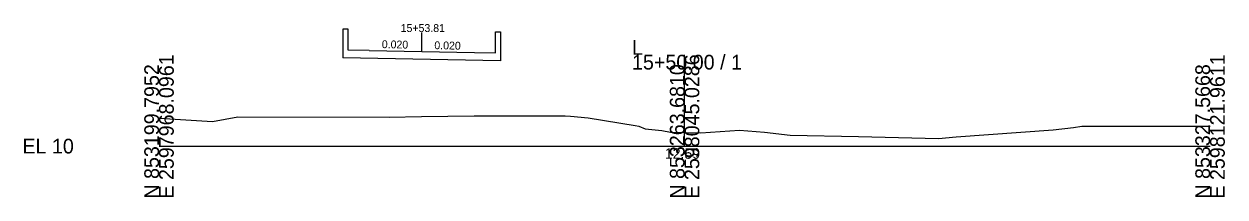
# Model space of a CAD drawing. Extents: x -26 to 1203, y -10 to 9526.
# Drawn here: x -25.7 to 202.8, y 5490.3 to 5523.3 of the extents above; entities that cross this region are included whole.
import ezdxf

# ---------------------------------------------------------------- set-up
doc = ezdxf.new("R2010")
doc.units = 0
for name, color, linetype in [('Exist Cross Section Cell', 7, 'Continuous'), ('Exist XS Center Line Elevation Label', 7, 'Continuous'), ('Exist XS Ground Line', 7, 'Continuous'), ('Prop XS Bridge', 7, 'Continuous'), ('Prop XS SE Text', 7, 'Continuous'), ('Prop XS Side Slope Text', 7, 'Continuous'), ('Prop XS Station Labels', 7, 'Continuous')]:
    doc.layers.add(name, color=color, linetype=linetype)

msp = doc.modelspace()

# ---------------------------------------------------------------- linework, layer by layer
at = {"layer": 'Exist Cross Section Cell'}
for p, q in [((100, 5500), (100, 5517.39)), ((0, 5500), (100, 5500)), ((100, 5500), (200, 5500))]:
    msp.add_line(p, q, dxfattribs=at)
at = {"layer": 'Exist XS Ground Line'}
for p, q in [((10.17, 5504.68), (14.97, 5505.56)), ((14.97, 5505.56), (43.76, 5505.49)), ((43.76, 5505.49), (49.97, 5505.66)), ((49.97, 5505.66), (59.97, 5505.8)), ((59.97, 5505.8), (77.29, 5505.78)), ((77.29, 5505.78), (78.31, 5505.73)), ((78.31, 5505.73), (81.67, 5505.42)), ((81.67, 5505.42), (90.6, 5503.9)), ((0, 5505.33), (10.17, 5504.68)), ((90.6, 5503.9), (91.3, 5503.77)), ((91.3, 5503.77), (92.5, 5503.29)), ((92.5, 5503.29), (95.65, 5502.96)), ((151.7, 5501.77), (170.16, 5503.08)), ((170.16, 5503.08), (174.01, 5503.57)), ((174.01, 5503.57), (175.58, 5503.8)), ((175.58, 5503.8), (181.13, 5503.8)), ((181.13, 5503.8), (198.66, 5503.81)), ((198.66, 5503.81), (200, 5503.83)), ((95.65, 5502.96), (97.32, 5502.66)), ((97.32, 5502.66), (100, 5502.59)), ((100, 5502.59), (103.07, 5502.51)), ((103.07, 5502.51), (110.48, 5503.04)), ((110.48, 5503.04), (115.23, 5502.63)), ((115.23, 5502.63), (120.08, 5502.07)), ((120.08, 5502.07), (133.11, 5501.84)), ((133.11, 5501.84), (148.33, 5501.46)), ((148.33, 5501.46), (151.7, 5501.77))]:
    msp.add_line(p, q, dxfattribs=at)
at = {"layer": 'Prop XS Bridge'}
for p, q in [((35, 5522.3), (35, 5518.3)), ((36, 5522.3), (35, 5522.3)), ((36, 5518.3), (36, 5522.3)), ((64, 5517.74), (64, 5521.74)), ((64, 5521.74), (65, 5521.74)), ((65, 5521.74), (65, 5517.74)), ((35, 5518.3), (35, 5516.8)), ((65, 5516.24), (35, 5516.8)), ((40, 5518.22), (36, 5518.3)), ((40, 5518.22), (50, 5518.02)), ((50, 5518.02), (60, 5517.82)), ((60, 5517.82), (64, 5517.74)), ((65, 5517.74), (65, 5516.24))]:
    msp.add_line(p, q, dxfattribs=at)
at = {"layer": 'Prop XS Side Slope Text'}
msp.add_line((50, 5518.02), (50, 5521.67), dxfattribs=at)

# ---------------------------------------------------------------- texts
at = {"layer": 'Exist Cross Section Cell'}
for s, p in [('L', (90, 5517.39)), ('15+50.00 / 1', (90, 5514.59)), ('EL 10', (-26, 5498.6))]:
    msp.add_text(s, height=2.8, dxfattribs=at).set_placement(p)
for s, p in [('E 2597968.0961', (2.8, 5490)), ('E 2598045.0286', (102.8, 5490)), ('E 2598121.9611', (202.8, 5490)), ('N 853199.7952', (0, 5490)), ('N 853263.6810', (100, 5490)), ('N 853327.5668', (200, 5490))]:
    msp.add_text(s, height=2.8, rotation=90, dxfattribs=at).set_placement(p)
at = {"layer": 'Exist XS Center Line Elevation Label'}
msp.add_text('12.59', height=2, dxfattribs=at).set_placement((96.26, 5497.59))
at = {"layer": 'Prop XS SE Text'}
for p in [(42.38, 5518.67), (52.38, 5518.47)]:
    msp.add_text('0.020', height=1.5, rotation=358.8542, dxfattribs=at).set_placement(p)
at = {"layer": 'Prop XS Station Labels'}
msp.add_text('15+53.81', height=1.5, dxfattribs=at).set_placement((45.98, 5521.74))

doc.saveas('drawing.dxf')
